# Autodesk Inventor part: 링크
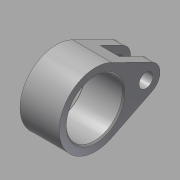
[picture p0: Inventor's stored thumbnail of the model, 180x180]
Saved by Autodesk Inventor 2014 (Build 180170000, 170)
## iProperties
Created: 2016-02
Part Number: 링크
Material: 강철, 연강
Document SubType Name: Modeling
Designer: test
Density: 7.86 g/cm^3
Appearance: 강철
Mass: 30.1156 g
Surface Area: 30.7911 cm^2
Volume: 3.8315 cm^3
Author: test
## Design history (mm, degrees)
sketch "스케치1"
  geometry: L1 (20.222, 4.479)-(5.778, 11.645); L2 (20.222, -4.479)-(5.778, -11.645); A1 r 13 centre (0, 0) between (5.778, 11.645) and (5.778, -11.645); A2 r 5 centre (18, 0) between (20.222, -4.479) and (20.222, 4.479); 1 further point
  constraints: 4 end point, 4 point on circle, 4 tangent, 2 centre point, 1 coincident, 1 horizontal alignment
  dimensions: "d0" = 18 distance of point (0, 0) A2.centre; "d1" = 13 radius of A1; "d2" = 5 radius of A2
extrude "돌출1" new body sketch "스케치1" stored distance "d3" = 14; taper "d4" = 0 deg
sketch "스케치2"
  geometry: C1 r 10 at (0, 0); 1 further point
  constraints: 1 centre point, 1 coincident
  dimensions: "d5" = 20 diameter of C1
extrude "돌출2" cut sketch "스케치2" stored distance "d6" = 14; taper "d7" = 0 deg
sketch "스케치3"
  geometry: C1 r 2.5 at (18, 0); A1 r 5 centre (18, 0) between (20.222, -4.479) and (20.222, 4.479) reference; 1 further point
  constraints: 1 centre point, 1 coincident
  dimensions: "d8" = 5 diameter of C1
extrude "돌출3" cut sketch "스케치3" stored distance "d9" = 14; taper "d10" = 0 deg
sketch "스케치4"
  geometry: L1 (20.222, -4.479)-(5.778, -11.645) reference; L2 (5.778, 11.645)-(20.222, 4.479) reference; L3 (12, 8.558)-(12, -8.558); C1 r 2.5 at (18, 0) reference; C2 r 10 at (0, 0) reference; A1 r 13 centre (0, 0) between (5.778, 11.645) and (5.778, -11.645) reference; A2 r 5 centre (18, 0) between (20.222, -4.479) and (20.222, 4.479) reference; 1 further point
  constraints: 2 end point, 2 point on line, 1 vertical
  dimensions: "d11" = 12 distance from line of L3 point (0, 0)
extrude "돌출4" cut sketch "스케치4" stored distance "d12" = 7; taper "d13" = 0 deg
chamfer "모따기1" distance "d14" = 0.5; stored, may be unused: second distance "d15" = 2, angle "d16" = 45 deg
node "솔리드1"
node "절단 모서리 투영1"
